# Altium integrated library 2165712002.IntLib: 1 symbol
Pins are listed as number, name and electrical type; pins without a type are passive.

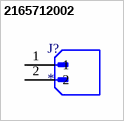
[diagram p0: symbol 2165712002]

## 2165712002
designator J?
Conn Wire to Board HDR 2 POS 3mm Solder ST Top Entry Thru-Hole Tray; MF: Molex; MP: 2165712002
footprint MOLEX_2165712002
pins: 1, 2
